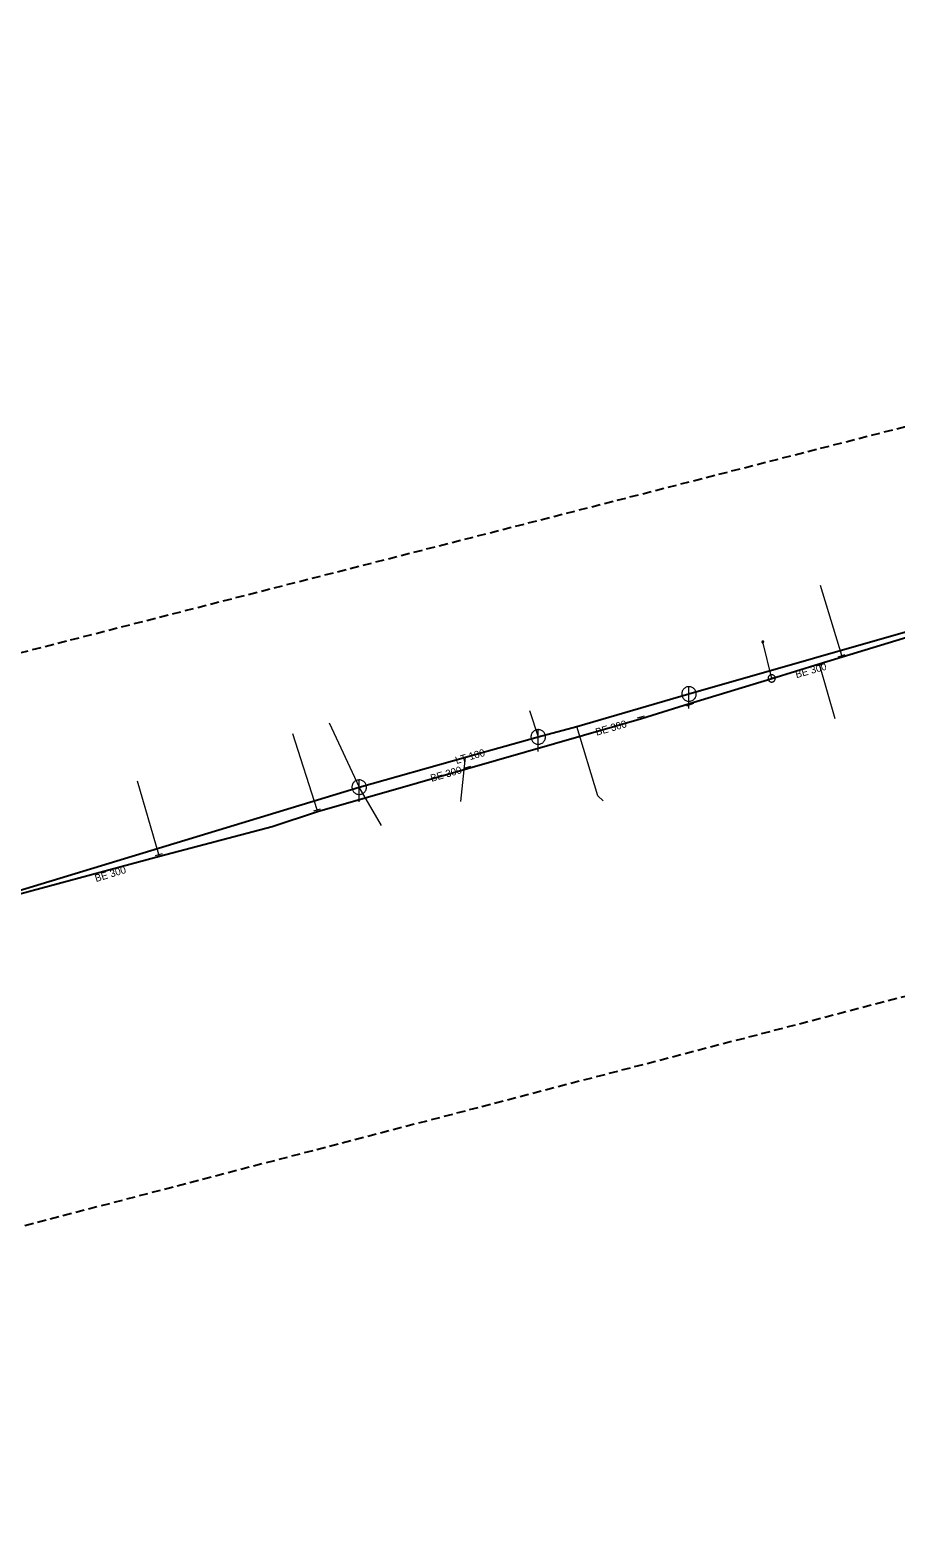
# Model space of a CAD drawing. Extents: x -690254 to -689100, y -975264 to -974703.
# Drawn here: x -689460.4 to -689341.6, y -974970.5 to -974763.7 of the extents above; entities that cross this region are included whole.
import ezdxf

# ---------------------------------------------------------------- set-up
doc = ezdxf.new("R2010")
doc.units = 0
doc.header["$LTSCALE"] = 0.4
doc.linetypes.add('MEDIUM_DASHED', pattern=[4.5, 3, -1.5])
for name, color, linetype, lineweight in [('1', 7, 'Continuous', 13), ('11', 7, 'Continuous', 13), ('13', 7, 'Continuous', 13), ('14', 7, 'Continuous', 13), ('17', 7, 'Continuous', 25), ('22', 7, 'Continuous', 13), ('34', 7, 'Continuous', 13), ('47', 7, 'Continuous', 13), ('63', 7, 'MEDIUM_DASHED', 25), ('9', 7, 'Continuous', 13)]:
    doc.layers.add(name, color=color, linetype=linetype, lineweight=lineweight)

msp = doc.modelspace()

# ---------------------------------------------------------------- linework, layer by layer
at = {"layer": '11'}
for p, q in [((-689391.868, -974857.029), (-689390.66, -974860.629)), ((-689419.34, -974858.706), (-689415.219, -974867.53)), ((-689401.271, -974869.486), (-689400.633, -974863.432)), ((-689412.168, -974872.764), (-689415.219, -974867.53))]:
    msp.add_line(p, q, dxfattribs=at)
msp.add_lwpolyline([(-689381.752, -974869.409), (-689382.487, -974868.719), (-689385.349, -974859.182)], dxfattribs=at)
at = {"layer": '13'}
for p, q in [((-689349.012, -974849.482), (-689351.932, -974839.875)), ((-689352.067, -974850.805), (-689349.952, -974858.098)), ((-689420.991, -974870.642), (-689424.344, -974860.205)), ((-689442.699, -974876.763), (-689445.642, -974866.695))]:
    msp.add_line(p, q, dxfattribs=at)
at = {"layer": '14'}
for p, q in [((-689358.632, -974852.602), (-689359.851, -974847.599)), ((-689348.96, -974849.653), (-689349.012, -974849.482)), ((-689352.123, -974850.624), (-689352.067, -974850.805)), ((-689369.914, -974856.032), (-689369.839, -974856.217)), ((-689376.509, -974858.111), (-689376.57, -974857.891)), ((-689400.344, -974864.98), (-689400.405, -974864.775)), ((-689420.942, -974870.852), (-689420.991, -974870.642)), ((-689442.62, -974876.987), (-689442.699, -974876.763))]:
    msp.add_line(p, q, dxfattribs=at)
at = {"layer": '14', "lineweight": 25}
for points in [[(-689390.66, -974860.629), (-689385.349, -974859.182), (-689369.98, -974854.739), (-689335.804, -974844.955), (-689284.956, -974830.167), (-689253.213, -974821.367)], [(-689415.219, -974867.53), (-689400.633, -974863.432), (-689390.66, -974860.629)], [(-689488.181, -974889.533), (-689482.829, -974888.039), (-689415.219, -974867.53)]]:
    msp.add_lwpolyline(points, dxfattribs=at)
at = {"layer": '17'}
for points in [[(-689358.632, -974852.602), (-689352.123, -974850.624), (-689348.96, -974849.653), (-689328.987, -974843.539), (-689279.795, -974829.994)], [(-689469.955, -974884.335), (-689442.62, -974876.987), (-689427.163, -974872.924), (-689420.942, -974870.852), (-689400.344, -974864.98), (-689376.509, -974858.111), (-689369.914, -974856.032), (-689358.632, -974852.602)]]:
    msp.add_lwpolyline(points, dxfattribs=at)
at = {"layer": '22'}
for p, q in [((-689369.98, -974856.74), (-689369.979, -974853.74)), ((-689390.66, -974862.63), (-689390.659, -974859.63)), ((-689415.22, -974869.53), (-689415.219, -974866.53))]:
    msp.add_line(p, q, dxfattribs=at)
for points in [[(-689368.98, -974854.74), (-689368.985, -974854.631), (-689369.003, -974854.523), (-689369.033, -974854.417), (-689369.073, -974854.316), (-689369.125, -974854.219), (-689369.187, -974854.129), (-689369.259, -974854.046), (-689369.339, -974853.972), (-689369.427, -974853.906), (-689369.521, -974853.851), (-689369.621, -974853.806), (-689369.726, -974853.773), (-689369.833, -974853.751), (-689369.942, -974853.741), (-689370.052, -974853.743), (-689370.16, -974853.757), (-689370.267, -974853.782), (-689370.37, -974853.819), (-689370.468, -974853.868), (-689370.56, -974853.926), (-689370.646, -974853.995), (-689370.723, -974854.072), (-689370.792, -974854.158), (-689370.851, -974854.25), (-689370.899, -974854.348), (-689370.936, -974854.451), (-689370.962, -974854.558), (-689370.976, -974854.666), (-689370.979, -974854.776), (-689370.969, -974854.885), (-689370.948, -974854.992), (-689370.914, -974855.096), (-689370.87, -974855.196), (-689370.815, -974855.291), (-689370.749, -974855.379), (-689370.675, -974855.459), (-689370.592, -974855.531), (-689370.502, -974855.593), (-689370.406, -974855.645), (-689370.304, -974855.686), (-689370.199, -974855.716), (-689370.091, -974855.734), (-689369.981, -974855.74), (-689369.872, -974855.734), (-689369.764, -974855.716), (-689369.659, -974855.687), (-689369.557, -974855.646), (-689369.46, -974855.594), (-689369.37, -974855.532), (-689369.287, -974855.461), (-689369.212, -974855.381), (-689369.147, -974855.293), (-689369.091, -974855.199), (-689369.047, -974855.099), (-689369.013, -974854.995), (-689368.991, -974854.887), (-689368.981, -974854.778)], [(-689389.66, -974860.63), (-689389.665, -974860.521), (-689389.683, -974860.413), (-689389.713, -974860.307), (-689389.753, -974860.206), (-689389.805, -974860.109), (-689389.867, -974860.019), (-689389.939, -974859.936), (-689390.019, -974859.862), (-689390.107, -974859.796), (-689390.201, -974859.741), (-689390.301, -974859.696), (-689390.406, -974859.663), (-689390.513, -974859.641), (-689390.622, -974859.631), (-689390.732, -974859.633), (-689390.84, -974859.647), (-689390.947, -974859.672), (-689391.05, -974859.709), (-689391.148, -974859.758), (-689391.24, -974859.816), (-689391.326, -974859.885), (-689391.403, -974859.962), (-689391.472, -974860.048), (-689391.531, -974860.14), (-689391.579, -974860.238), (-689391.616, -974860.341), (-689391.642, -974860.448), (-689391.656, -974860.556), (-689391.659, -974860.666), (-689391.649, -974860.775), (-689391.628, -974860.882), (-689391.594, -974860.986), (-689391.55, -974861.086), (-689391.495, -974861.181), (-689391.429, -974861.269), (-689391.355, -974861.349), (-689391.272, -974861.421), (-689391.182, -974861.483), (-689391.086, -974861.535), (-689390.984, -974861.576), (-689390.879, -974861.606), (-689390.771, -974861.624), (-689390.661, -974861.63), (-689390.552, -974861.624), (-689390.444, -974861.606), (-689390.339, -974861.577), (-689390.237, -974861.536), (-689390.14, -974861.484), (-689390.05, -974861.422), (-689389.967, -974861.351), (-689389.892, -974861.271), (-689389.827, -974861.183), (-689389.771, -974861.089), (-689389.727, -974860.989), (-689389.693, -974860.885), (-689389.671, -974860.777), (-689389.661, -974860.668)], [(-689414.22, -974867.53), (-689414.225, -974867.421), (-689414.243, -974867.313), (-689414.273, -974867.207), (-689414.313, -974867.106), (-689414.365, -974867.009), (-689414.427, -974866.919), (-689414.499, -974866.836), (-689414.579, -974866.762), (-689414.667, -974866.696), (-689414.761, -974866.641), (-689414.861, -974866.596), (-689414.966, -974866.563), (-689415.073, -974866.541), (-689415.182, -974866.531), (-689415.292, -974866.533), (-689415.4, -974866.547), (-689415.507, -974866.572), (-689415.61, -974866.609), (-689415.708, -974866.658), (-689415.8, -974866.716), (-689415.886, -974866.785), (-689415.963, -974866.862), (-689416.032, -974866.948), (-689416.091, -974867.04), (-689416.139, -974867.138), (-689416.176, -974867.241), (-689416.202, -974867.348), (-689416.216, -974867.456), (-689416.219, -974867.566), (-689416.209, -974867.675), (-689416.188, -974867.782), (-689416.154, -974867.886), (-689416.11, -974867.986), (-689416.055, -974868.081), (-689415.989, -974868.169), (-689415.915, -974868.249), (-689415.832, -974868.321), (-689415.742, -974868.383), (-689415.646, -974868.435), (-689415.544, -974868.476), (-689415.439, -974868.506), (-689415.331, -974868.524), (-689415.221, -974868.53), (-689415.112, -974868.524), (-689415.004, -974868.506), (-689414.899, -974868.477), (-689414.797, -974868.436), (-689414.7, -974868.384), (-689414.61, -974868.322), (-689414.527, -974868.251), (-689414.452, -974868.171), (-689414.387, -974868.083), (-689414.331, -974867.989), (-689414.287, -974867.889), (-689414.253, -974867.785), (-689414.231, -974867.677), (-689414.221, -974867.568)]]:
    msp.add_lwpolyline(points, close=True, dxfattribs=at)
at = {"layer": '34'}
for p, q in [((-689349.489, -974849.629), (-689348.533, -974849.335)), ((-689351.586, -974850.665), (-689352.547, -974850.943)), ((-689369.375, -974856.029), (-689370.302, -974856.403)), ((-689377.051, -974858.026), (-689376.088, -974857.756)), ((-689400.884, -974864.917), (-689399.925, -974864.633)), ((-689421.466, -974870.795), (-689420.514, -974870.489)), ((-689443.178, -974876.903), (-689442.218, -974876.623))]:
    msp.add_line(p, q, dxfattribs=at)
at = {"layer": '47'}
for points in [[(-689358.153, -974852.456), (-689358.171, -974852.407), (-689358.194, -974852.36), (-689358.222, -974852.316), (-689358.253, -974852.274), (-689358.29, -974852.236), (-689358.33, -974852.203), (-689358.374, -974852.174), (-689358.42, -974852.149), (-689358.468, -974852.129), (-689358.518, -974852.115), (-689358.57, -974852.105), (-689358.622, -974852.102), (-689358.674, -974852.103), (-689358.726, -974852.111), (-689358.777, -974852.123), (-689358.826, -974852.141), (-689358.873, -974852.164), (-689358.918, -974852.192), (-689358.959, -974852.223), (-689358.997, -974852.26), (-689359.03, -974852.3), (-689359.06, -974852.344), (-689359.085, -974852.39), (-689359.105, -974852.438), (-689359.118, -974852.488), (-689359.128, -974852.54), (-689359.132, -974852.593), (-689359.13, -974852.644), (-689359.122, -974852.696), (-689359.11, -974852.747), (-689359.092, -974852.796), (-689359.069, -974852.843), (-689359.042, -974852.888), (-689359.01, -974852.929), (-689358.973, -974852.967), (-689358.933, -974853.001), (-689358.89, -974853.03), (-689358.844, -974853.055), (-689358.795, -974853.075), (-689358.745, -974853.088), (-689358.693, -974853.098), (-689358.641, -974853.102), (-689358.589, -974853.1), (-689358.537, -974853.092), (-689358.486, -974853.08), (-689358.437, -974853.062), (-689358.39, -974853.039), (-689358.346, -974853.012), (-689358.304, -974852.98), (-689358.266, -974852.943), (-689358.232, -974852.903), (-689358.204, -974852.86), (-689358.179, -974852.814), (-689358.159, -974852.765), (-689358.145, -974852.715), (-689358.135, -974852.663), (-689358.132, -974852.612), (-689358.133, -974852.559), (-689358.141, -974852.507)], [(-689358.553, -974852.578), (-689358.556, -974852.569), (-689358.56, -974852.562), (-689358.564, -974852.555), (-689358.569, -974852.548), (-689358.575, -974852.542), (-689358.582, -974852.536), (-689358.589, -974852.531), (-689358.597, -974852.527), (-689358.605, -974852.524), (-689358.613, -974852.522), (-689358.622, -974852.52), (-689358.63, -974852.52), (-689358.639, -974852.52), (-689358.647, -974852.52), (-689358.655, -974852.523), (-689358.664, -974852.526), (-689358.671, -974852.53), (-689358.678, -974852.534), (-689358.685, -974852.539), (-689358.691, -974852.545), (-689358.697, -974852.552), (-689358.702, -974852.559), (-689358.706, -974852.567), (-689358.71, -974852.575), (-689358.711, -974852.583), (-689358.713, -974852.592), (-689358.713, -974852.6), (-689358.713, -974852.609), (-689358.713, -974852.617), (-689358.71, -974852.625), (-689358.707, -974852.634), (-689358.703, -974852.641), (-689358.699, -974852.648), (-689358.694, -974852.655), (-689358.688, -974852.661), (-689358.682, -974852.667), (-689358.674, -974852.672), (-689358.666, -974852.676), (-689358.658, -974852.68), (-689358.65, -974852.681), (-689358.641, -974852.683), (-689358.633, -974852.683), (-689358.624, -974852.683), (-689358.616, -974852.683), (-689358.608, -974852.68), (-689358.599, -974852.677), (-689358.592, -974852.673), (-689358.585, -974852.669), (-689358.578, -974852.664), (-689358.572, -974852.658), (-689358.566, -974852.652), (-689358.561, -974852.644), (-689358.557, -974852.636), (-689358.554, -974852.628), (-689358.552, -974852.62), (-689358.55, -974852.611), (-689358.55, -974852.603), (-689358.55, -974852.594), (-689358.55, -974852.586)]]:
    msp.add_lwpolyline(points, close=True, dxfattribs=at)
at = {"layer": '63'}
msp.add_lwpolyline([(-690175.832, -975238.167), (-690201.511, -975156.663), (-690201.511, -975156.663), (-689696.859, -975008.171), (-689696.859, -975008.171), (-689730.354, -974917.735), (-689730.354, -974917.735), (-689127.452, -974763.66), (-689127.452, -974763.66), (-689118.52, -974838.465), (-689118.52, -974838.465), (-689624.288, -974970.21), (-689624.288, -974970.21), (-689593.026, -975070.694), (-689593.026, -975070.694)], close=True, dxfattribs=at)
at = {"layer": '9'}
for points in [[(-689359.977, -974847.599), (-689359.977, -974847.612), (-689359.975, -974847.625), (-689359.972, -974847.638), (-689359.967, -974847.65), (-689359.961, -974847.662), (-689359.954, -974847.673), (-689359.946, -974847.683), (-689359.936, -974847.693), (-689359.926, -974847.701), (-689359.915, -974847.708), (-689359.903, -974847.714), (-689359.891, -974847.719), (-689359.878, -974847.722), (-689359.865, -974847.724), (-689359.852, -974847.726), (-689359.839, -974847.725), (-689359.826, -974847.723), (-689359.813, -974847.72), (-689359.801, -974847.715), (-689359.789, -974847.709), (-689359.778, -974847.702), (-689359.768, -974847.694), (-689359.758, -974847.684), (-689359.75, -974847.674), (-689359.743, -974847.663), (-689359.737, -974847.651), (-689359.732, -974847.639), (-689359.729, -974847.626), (-689359.727, -974847.613), (-689359.725, -974847.6), (-689359.726, -974847.587), (-689359.728, -974847.574), (-689359.731, -974847.561), (-689359.736, -974847.549), (-689359.742, -974847.537), (-689359.749, -974847.526), (-689359.757, -974847.516), (-689359.767, -974847.506), (-689359.777, -974847.498), (-689359.788, -974847.491), (-689359.8, -974847.485), (-689359.812, -974847.48), (-689359.825, -974847.477), (-689359.838, -974847.475), (-689359.851, -974847.474), (-689359.864, -974847.474), (-689359.877, -974847.476), (-689359.89, -974847.479), (-689359.902, -974847.484), (-689359.914, -974847.49), (-689359.925, -974847.497), (-689359.935, -974847.505), (-689359.945, -974847.515), (-689359.953, -974847.525), (-689359.96, -974847.536), (-689359.966, -974847.548), (-689359.971, -974847.56), (-689359.974, -974847.573), (-689359.976, -974847.586)], [(-689359.957, -974847.599), (-689359.958, -974847.61), (-689359.956, -974847.621), (-689359.953, -974847.632), (-689359.949, -974847.642), (-689359.944, -974847.652), (-689359.938, -974847.661), (-689359.931, -974847.67), (-689359.923, -974847.678), (-689359.914, -974847.685), (-689359.905, -974847.691), (-689359.895, -974847.696), (-689359.885, -974847.7), (-689359.874, -974847.703), (-689359.863, -974847.706), (-689359.852, -974847.706), (-689359.841, -974847.706), (-689359.83, -974847.704), (-689359.819, -974847.701), (-689359.809, -974847.697), (-689359.799, -974847.692), (-689359.79, -974847.686), (-689359.781, -974847.679), (-689359.773, -974847.671), (-689359.766, -974847.662), (-689359.76, -974847.653), (-689359.755, -974847.643), (-689359.751, -974847.633), (-689359.748, -974847.622), (-689359.746, -974847.611), (-689359.745, -974847.6), (-689359.745, -974847.589), (-689359.747, -974847.578), (-689359.75, -974847.567), (-689359.754, -974847.557), (-689359.759, -974847.547), (-689359.765, -974847.538), (-689359.772, -974847.529), (-689359.78, -974847.521), (-689359.789, -974847.514), (-689359.798, -974847.508), (-689359.808, -974847.503), (-689359.818, -974847.499), (-689359.829, -974847.496), (-689359.84, -974847.494), (-689359.851, -974847.494), (-689359.862, -974847.493), (-689359.873, -974847.495), (-689359.884, -974847.498), (-689359.894, -974847.502), (-689359.904, -974847.507), (-689359.913, -974847.513), (-689359.922, -974847.52), (-689359.93, -974847.528), (-689359.937, -974847.537), (-689359.943, -974847.546), (-689359.948, -974847.556), (-689359.952, -974847.566), (-689359.955, -974847.577), (-689359.957, -974847.588)], [(-689359.938, -974847.599), (-689359.938, -974847.608), (-689359.937, -974847.617), (-689359.934, -974847.626), (-689359.931, -974847.634), (-689359.927, -974847.642), (-689359.922, -974847.65), (-689359.916, -974847.657), (-689359.91, -974847.663), (-689359.903, -974847.669), (-689359.895, -974847.674), (-689359.887, -974847.678), (-689359.879, -974847.681), (-689359.87, -974847.684), (-689359.861, -974847.685), (-689359.852, -974847.687), (-689359.843, -974847.686), (-689359.834, -974847.685), (-689359.825, -974847.682), (-689359.817, -974847.679), (-689359.809, -974847.675), (-689359.801, -974847.67), (-689359.794, -974847.664), (-689359.788, -974847.658), (-689359.782, -974847.651), (-689359.777, -974847.643), (-689359.773, -974847.635), (-689359.77, -974847.627), (-689359.767, -974847.618), (-689359.766, -974847.609), (-689359.764, -974847.6), (-689359.765, -974847.591), (-689359.766, -974847.582), (-689359.769, -974847.573), (-689359.772, -974847.565), (-689359.776, -974847.557), (-689359.781, -974847.549), (-689359.787, -974847.542), (-689359.793, -974847.536), (-689359.8, -974847.53), (-689359.808, -974847.525), (-689359.816, -974847.521), (-689359.824, -974847.518), (-689359.833, -974847.515), (-689359.842, -974847.514), (-689359.851, -974847.513), (-689359.86, -974847.513), (-689359.869, -974847.514), (-689359.878, -974847.517), (-689359.886, -974847.52), (-689359.894, -974847.524), (-689359.902, -974847.529), (-689359.909, -974847.535), (-689359.915, -974847.541), (-689359.921, -974847.548), (-689359.926, -974847.556), (-689359.93, -974847.564), (-689359.933, -974847.572), (-689359.936, -974847.581), (-689359.937, -974847.59)], [(-689359.918, -974847.599), (-689359.918, -974847.606), (-689359.917, -974847.613), (-689359.916, -974847.62), (-689359.913, -974847.626), (-689359.91, -974847.632), (-689359.906, -974847.638), (-689359.902, -974847.644), (-689359.897, -974847.649), (-689359.891, -974847.653), (-689359.885, -974847.657), (-689359.879, -974847.66), (-689359.873, -974847.663), (-689359.866, -974847.664), (-689359.859, -974847.667), (-689359.852, -974847.667), (-689359.845, -974847.667), (-689359.838, -974847.665), (-689359.831, -974847.664), (-689359.825, -974847.661), (-689359.818, -974847.658), (-689359.813, -974847.654), (-689359.807, -974847.65), (-689359.802, -974847.645), (-689359.798, -974847.639), (-689359.794, -974847.633), (-689359.791, -974847.627), (-689359.788, -974847.621), (-689359.786, -974847.614), (-689359.785, -974847.607), (-689359.784, -974847.6), (-689359.784, -974847.593), (-689359.785, -974847.586), (-689359.787, -974847.579), (-689359.79, -974847.573), (-689359.793, -974847.566), (-689359.797, -974847.561), (-689359.801, -974847.555), (-689359.806, -974847.55), (-689359.812, -974847.546), (-689359.817, -974847.542), (-689359.824, -974847.539), (-689359.83, -974847.536), (-689359.837, -974847.534), (-689359.844, -974847.533), (-689359.851, -974847.533), (-689359.858, -974847.533), (-689359.865, -974847.533), (-689359.872, -974847.535), (-689359.878, -974847.538), (-689359.884, -974847.541), (-689359.89, -974847.545), (-689359.896, -974847.549), (-689359.901, -974847.554), (-689359.905, -974847.56), (-689359.909, -974847.565), (-689359.912, -974847.572), (-689359.915, -974847.578), (-689359.916, -974847.585), (-689359.918, -974847.592)], [(-689359.898, -974847.599), (-689359.898, -974847.604), (-689359.898, -974847.609), (-689359.897, -974847.614), (-689359.895, -974847.618), (-689359.893, -974847.623), (-689359.89, -974847.627), (-689359.887, -974847.63), (-689359.883, -974847.634), (-689359.88, -974847.637), (-689359.876, -974847.64), (-689359.871, -974847.642), (-689359.867, -974847.644), (-689359.862, -974847.645), (-689359.857, -974847.647), (-689359.852, -974847.647), (-689359.847, -974847.647), (-689359.842, -974847.646), (-689359.837, -974847.645), (-689359.833, -974847.643), (-689359.828, -974847.641), (-689359.824, -974847.638), (-689359.82, -974847.635), (-689359.817, -974847.631), (-689359.814, -974847.628), (-689359.811, -974847.624), (-689359.809, -974847.619), (-689359.807, -974847.615), (-689359.806, -974847.61), (-689359.805, -974847.605), (-689359.804, -974847.6), (-689359.804, -974847.595), (-689359.805, -974847.59), (-689359.806, -974847.585), (-689359.808, -974847.581), (-689359.81, -974847.576), (-689359.813, -974847.572), (-689359.816, -974847.568), (-689359.819, -974847.565), (-689359.823, -974847.562), (-689359.827, -974847.559), (-689359.832, -974847.557), (-689359.836, -974847.555), (-689359.841, -974847.554), (-689359.846, -974847.553), (-689359.851, -974847.553), (-689359.856, -974847.553), (-689359.861, -974847.554), (-689359.866, -974847.554), (-689359.87, -974847.556), (-689359.875, -974847.558), (-689359.879, -974847.561), (-689359.882, -974847.564), (-689359.886, -974847.567), (-689359.889, -974847.571), (-689359.892, -974847.575), (-689359.894, -974847.58), (-689359.896, -974847.584), (-689359.897, -974847.589), (-689359.898, -974847.594)], [(-689359.878, -974847.599), (-689359.878, -974847.602), (-689359.879, -974847.605), (-689359.878, -974847.607), (-689359.877, -974847.61), (-689359.876, -974847.613), (-689359.874, -974847.615), (-689359.872, -974847.617), (-689359.87, -974847.619), (-689359.868, -974847.621), (-689359.866, -974847.623), (-689359.863, -974847.625), (-689359.86, -974847.626), (-689359.858, -974847.626), (-689359.855, -974847.627), (-689359.852, -974847.627), (-689359.849, -974847.627), (-689359.846, -974847.627), (-689359.843, -974847.626), (-689359.841, -974847.625), (-689359.838, -974847.624), (-689359.836, -974847.622), (-689359.833, -974847.62), (-689359.831, -974847.618), (-689359.83, -974847.616), (-689359.828, -974847.614), (-689359.827, -974847.611), (-689359.825, -974847.608), (-689359.825, -974847.606), (-689359.824, -974847.603), (-689359.823, -974847.6), (-689359.824, -974847.597), (-689359.824, -974847.594), (-689359.825, -974847.591), (-689359.826, -974847.589), (-689359.827, -974847.586), (-689359.829, -974847.584), (-689359.83, -974847.581), (-689359.832, -974847.579), (-689359.835, -974847.578), (-689359.837, -974847.576), (-689359.84, -974847.575), (-689359.842, -974847.574), (-689359.845, -974847.573), (-689359.848, -974847.573), (-689359.851, -974847.572), (-689359.854, -974847.573), (-689359.857, -974847.572), (-689359.859, -974847.574), (-689359.862, -974847.574), (-689359.865, -974847.575), (-689359.867, -974847.577), (-689359.869, -974847.578), (-689359.871, -974847.58), (-689359.873, -974847.583), (-689359.875, -974847.585), (-689359.876, -974847.588), (-689359.877, -974847.59), (-689359.878, -974847.593), (-689359.878, -974847.596)], [(-689359.859, -974847.599), (-689359.859, -974847.601), (-689359.859, -974847.601), (-689359.858, -974847.601), (-689359.858, -974847.603), (-689359.859, -974847.604), (-689359.857, -974847.604), (-689359.857, -974847.604), (-689359.857, -974847.606), (-689359.857, -974847.606), (-689359.856, -974847.607), (-689359.854, -974847.607), (-689359.854, -974847.607), (-689359.854, -974847.608), (-689359.852, -974847.608), (-689359.852, -974847.608), (-689359.851, -974847.608), (-689359.85, -974847.608), (-689359.85, -974847.607), (-689359.849, -974847.607), (-689359.847, -974847.607), (-689359.847, -974847.606), (-689359.847, -974847.606), (-689359.846, -974847.605), (-689359.846, -974847.605), (-689359.844, -974847.604), (-689359.844, -974847.603), (-689359.843, -974847.602), (-689359.843, -974847.602), (-689359.843, -974847.601), (-689359.843, -974847.6), (-689359.843, -974847.599), (-689359.843, -974847.598), (-689359.843, -974847.598), (-689359.844, -974847.597), (-689359.844, -974847.596), (-689359.845, -974847.595), (-689359.845, -974847.595), (-689359.846, -974847.594), (-689359.846, -974847.594), (-689359.847, -974847.593), (-689359.848, -974847.593), (-689359.849, -974847.592), (-689359.849, -974847.592), (-689359.85, -974847.592), (-689359.851, -974847.592), (-689359.852, -974847.592), (-689359.853, -974847.592), (-689359.853, -974847.592), (-689359.854, -974847.593), (-689359.855, -974847.592), (-689359.856, -974847.594), (-689359.856, -974847.594), (-689359.857, -974847.594), (-689359.857, -974847.594), (-689359.858, -974847.596), (-689359.858, -974847.597), (-689359.858, -974847.598), (-689359.859, -974847.598), (-689359.859, -974847.599)]]:
    msp.add_lwpolyline(points, close=True, dxfattribs=at)

# ---------------------------------------------------------------- texts
at = {"layer": '1'}
for s, rotation, p in [('BE 300', 16, (-689355.229, -974852.581)), ('BE 300', 16, (-689382.643, -974860.476)), ('LT 100', 16, (-689401.88, -974864.36)), ('BE 300', 16, (-689405.29, -974866.801)), ('BE 300', 17, (-689451.318, -974880.555))]:
    msp.add_text(s, height=1, rotation=rotation, dxfattribs=at).set_placement(p)

doc.saveas('drawing.dxf')
